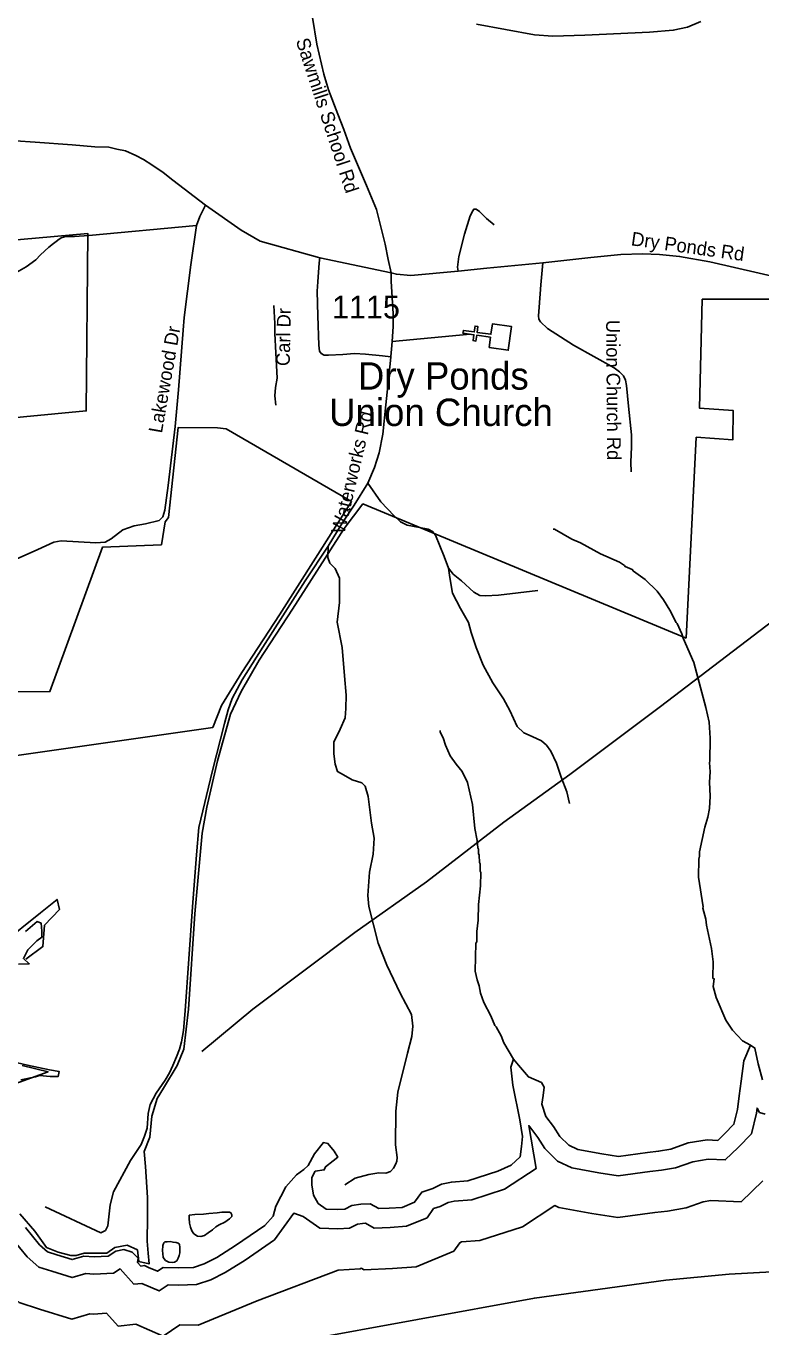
# Model space of a CAD drawing. Extents: x 1159738 to 1321356, y 736314 to 882035.
# Drawn here: x 1262980 to 1267008, y 749048 to 756175 of the extents above; entities that cross this region are included whole.
import ezdxf

# ---------------------------------------------------------------- set-up
doc = ezdxf.new("R2010")
doc.units = 0
for name, color, linetype in [('Exist Boundary Political City Limit New', 7, 'Continuous'), ('Exist Boundary Political CountyLine', 7, 'Continuous'), ('Exist Cultural Church CELL', 7, 'Continuous'), ('Exist Cultural Church Label', 7, 'Continuous'), ('Exist Hydrographic Buffer Line', 7, 'Continuous'), ('Exist Hydrographic Lake Shore', 7, 'Continuous'), ('Exist Hydrographic Misc Water Feature', 7, 'Continuous'), ('Exist Road Non-System Type 51', 7, 'Continuous'), ('Exist Road Non-System Type 51 Label', 7, 'Continuous'), ('Exist Road Secondary Type 51 Attributed', 7, 'Continuous'), ('Exist Road Secondary Type 51 Label', 7, 'Continuous'), ('Exist Road Secondary Type 51 Number Label', 7, 'Continuous'), ('Exist Utilities Electrical Transmission Line', 7, 'Continuous'), ('Map Preparation Boundary City Limit Buffer Line', 7, 'Continuous')]:
    doc.layers.add(name, color=color, linetype=linetype)

msp = doc.modelspace()

# ---------------------------------------------------------------- linework, layer by layer
at = {"layer": 'Exist Boundary Political City Limit New'}
for points in [[(1262145.2, 753954.7), (1263309.9, 754066.5), (1263318.5, 755038.6), (1262292, 754947.9)], [(1267932.2, 754678), (1266685.8, 754678), (1266670.3, 754081.6), (1266855.1, 754068.7), (1266854.7, 753908.1), (1266653.1, 753922.4), (1266597.3, 752821.4)], [(1262276.5, 752084.9), (1264003.4, 752333), (1264050.7, 752453.4), (1264162.4, 752634.1), (1264368.7, 752950.2), (1264764.1, 753569.5), (1264076.7, 753968.4), (1264030, 753973.5), (1263813.2, 753974.9), (1263761.6, 753482.5), (1263742.3, 753458.8), (1263721.9, 753333), (1263399.5, 753320.1), (1263111.5, 752528.7), (1262428.2, 752524.4)], [(1266597.3, 752821.4), (1264826.5, 753556.9), (1264723.3, 753421.4), (1264440.2, 752980.1), (1264257.5, 752700.6), (1264158.6, 752528.5), (1264100.6, 752406), (1264029.9, 752149.2), (1263971.9, 751895.4), (1263946.1, 751753.5), (1263905.3, 751311.5), (1263870.9, 750788.9), (1263845.1, 750569.6), (1263809, 750481), (1263733.8, 750356.3), (1263699.4, 750300.4), (1263669.3, 750203.6), (1263658.6, 750087.5), (1263628.5, 750010.1), (1263635, 749927.1), (1263645.7, 749757.2), (1263645.7, 749647.5), (1263643.6, 749518.5), (1263650, 749451.8), (1263654.3, 749393.8), (1263598.5, 749406.7), (1263590.9, 749470.1), (1263535.1, 749495.9), (1263466.3, 749483), (1263423.3, 749452.9), (1263376, 749452.9), (1263298.7, 749452.9), (1263255.7, 749440), (1263225.6, 749440), (1263156.8, 749457.2), (1263092.4, 749483), (1263027.9, 749573.3), (1262946.2, 749667.9)], [(1262978.5, 751063.6), (1263073, 751132.4), (1263081.6, 751248.6), (1263163.3, 751334.6), (1263150.4, 751390.5), (1263060.1, 751317.4), (1262845.2, 751145.3)], [(1262899, 750373.3), (1263101, 750446.4), (1262959.1, 750480.8)]]:
    msp.add_lwpolyline(points, dxfattribs=at)
at = {"layer": 'Exist Boundary Political CountyLine'}
msp.add_lwpolyline([(1275487.7, 746396.7), (1275208.4, 749051.3), (1275206, 749131.4), (1275197.6, 749211.6), (1275176.8, 749268.1), (1275147.5, 749306.7), (1275000.3, 749445.7), (1274913.6, 749513.5), (1274703.9, 749631.8), (1274606.5, 749663.7), (1274512.7, 749675.6), (1273414.6, 749697.7), (1266834.1, 749337.5), (1266487.3, 749304.4), (1265766.9, 749206.8), (1263842.9, 748855.2), (1262274.7, 748482.5)], dxfattribs=at)
at = {"layer": 'Exist Cultural Church CELL'}
msp.add_lwpolyline([(1265517.8, 754413.8), (1265525.7, 754470.2), (1265450.3, 754480.9), (1265445.8, 754449.3), (1265430, 754451.5), (1265434.5, 754483.2), (1265375, 754491.7), (1265377.2, 754507.6), (1265436.8, 754499.1), (1265441.3, 754530.7), (1265457.1, 754528.5), (1265452.6, 754496.8), (1265528, 754486), (1265536.2, 754543.1), (1265641.6, 754528), (1265623.1, 754398.7)], close=True, dxfattribs=at)
at = {"layer": 'Exist Hydrographic Buffer Line'}
for points in [[(1267031.8, 750213.2), (1267000.6, 750223.6), (1266986.7, 750246.9), (1266983.2, 750220.2), (1266955.4, 750105.5), (1266882.5, 750031.4), (1266812.3, 749963.4), (1266718.8, 749967.2), (1266635.3, 749953.7), (1266540.3, 749920.6), (1266462.6, 749906.6), (1266399, 749899.2), (1266226.3, 749875.9), (1266119, 749892.7), (1265971, 749919.3), (1265893.6, 749956.9), (1265823.2, 750025.2), (1265784.6, 750086.7), (1265735.1, 750151.7), (1265775.5, 749915.6), (1265603.4, 749802.8), (1265422.6, 749744.8), (1265326.8, 749737.3), (1265293.1, 749729.9), (1265250.4, 749708.1), (1265214.2, 749696.8), (1265178, 749646.4), (1265065.5, 749599.6), (1264975.6, 749593.6), (1264887.9, 749589.9), (1264841.4, 749616), (1264825.2, 749615.2), (1264797.3, 749611.2), (1264753.9, 749590.1), (1264688.6, 749586.2), (1264589.8, 749589.9), (1264499.8, 749652.9), (1264448.5, 749672.5), (1264342, 749525.3)], [(1263923.6, 749057.9), (1263823.9, 749059.8), (1263732.1, 748998.2), (1263582.1, 749063.7), (1263485.7, 749052), (1263421.7, 749122.9), (1263350.4, 749118.4), (1263330, 749120.2), (1263231.1, 749090.7), (1263055, 749145.9), (1262942, 749182.5), (1262828.9, 749280), (1262733.9, 749397), (1262697.7, 749441.7), (1262618.3, 749509.7), (1262443.9, 749710.6), (1262387.6, 749882.1)], [(1267018.5, 749848.9), (1266900, 749733.9), (1266732.4, 749740.7), (1266690.8, 749734), (1266597.8, 749701.6), (1266495.7, 749683.3), (1266427.2, 749675.3), (1266223.8, 749647.8), (1266081.5, 749670.1), (1265900.5, 749702.7), (1265878.6, 749713.3), (1265701.5, 749597.3), (1265466.6, 749521.9), (1265366.7, 749514), (1265357.4, 749509.3), (1265324, 749462.6), (1265117.7, 749376.9), (1264987.9, 749368.2), (1264833.3, 749361.7), (1264817.9, 749370.3), (1264812.2, 749367.5), (1264691.2, 749360.2), (1264247.8, 749191.3), (1263923.6, 749057.9)], [(1264342, 749525.3), (1264180.6, 749414.5), (1264072.5, 749347.1), (1263993.4, 749306), (1263914.1, 749280.3), (1263815.5, 749277.5), (1263759.7, 749279.1), (1263709.8, 749245.6), (1263614.8, 749287), (1263571.7, 749281.8), (1263495.8, 749366.1), (1263459.9, 749343.6), (1263352.7, 749336.8), (1263307.2, 749340.7), (1263232.7, 749318.5), (1263121.1, 749353.5), (1263050.9, 749376.2), (1262985.8, 749432.3), (1262903.1, 749534.2)]]:
    msp.add_lwpolyline(points, dxfattribs=at)
at = {"layer": 'Exist Hydrographic Lake Shore'}
for points in [[(1262939.9, 751035.4), (1262997.6, 751037.8), (1262965.7, 751066.4), (1262990.3, 751114), (1263039.4, 751164.1), (1263066.4, 751183.1), (1263066.4, 751216.5), (1263063.9, 751259.4), (1263041.8, 751268.9), (1262978, 751214.1)], [(1267017, 750401.6), (1266992.5, 750489.8), (1266975.3, 750575.6), (1266950.7, 750592.3), (1266913.9, 750506.5), (1266899.1, 750394.5), (1266889.3, 750313.5), (1266879.5, 750239.6), (1266859.8, 750158.6), (1266808.3, 750106.2), (1266771.4, 750070.5), (1266712.5, 750072.9), (1266609.3, 750056.2), (1266513.5, 750022.8), (1266447.2, 750010.9), (1266385.8, 750003.8), (1266227.4, 749982.3), (1266136.5, 749996.6), (1266003.9, 750020.4), (1265954.8, 750044.3), (1265905.7, 750091.9), (1265871.3, 750146.7), (1265829.5, 750201.5), (1265807.4, 750268.2), (1265814.8, 750315.9), (1265819.7, 750361.1), (1265805, 750387.4), (1265733.7, 750418.3), (1265679.7, 750482.7), (1265651.4, 750516), (1265636.7, 750470.7), (1265649, 750373.1), (1265685.8, 750182.5), (1265700.6, 750091.9), (1265695.7, 750037.1), (1265688.3, 749979.9), (1265639.2, 749934.7), (1265565.5, 749901.3), (1265402.1, 749848.9), (1265311.3, 749841.7), (1265257.2, 749829.8), (1265210.6, 749806), (1265149.2, 749786.9), (1265109.9, 749732.1), (1265041.1, 749703.5), (1264969.9, 749698.8), (1264913.4, 749696.4), (1264866.7, 749722.6), (1264815.1, 749720.2), (1264766, 749713.1), (1264726.7, 749694), (1264687.4, 749691.6), (1264624.8, 749694), (1264580.6, 749725), (1264556, 749770.3), (1264546.2, 749827.4), (1264546.2, 749867.9), (1264565.8, 749901.3), (1264615, 749908.5), (1264621.6, 749926.3), (1264663.6, 749959), (1264688.7, 749977.5), (1264669, 750010.9), (1264634.6, 750053.8), (1264610.1, 750058.6), (1264560.9, 749996.6), (1264526.5, 749932.3), (1264502, 749910.8), (1264462.7, 749882.2), (1264403.7, 749815.5), (1264349.7, 749710.7), (1264335, 749655.9), (1264288.3, 749603.5)], [(1262951, 750401.6), (1263032, 750418.3), (1263054.1, 750425.5), (1263113.1, 750420.7), (1263157.3, 750420.7), (1263162.2, 750446.9), (1263108.1, 750456.4), (1262989, 750482.7), (1262871.1, 750508.9)], [(1264288.3, 749603.5), (1264128.7, 749493.9), (1264025.5, 749429.5), (1263956.7, 749393.8), (1263897.8, 749374.7), (1263815.5, 749372.4), (1263732, 749374.7), (1263700.1, 749353.3), (1263650.9, 749374.7), (1263628.8, 749384.3), (1263609.2, 749381.9), (1263592, 749401), (1263594.5, 749424.8), (1263562.5, 749458.1), (1263515.9, 749472.4), (1263471.6, 749462.9), (1263429.9, 749436.7), (1263353.8, 749431.9), (1263297.3, 749436.7), (1263233.4, 749417.6), (1263149.9, 749443.8), (1263098.3, 749460.5), (1263054.1, 749498.6), (1262976.7, 749593.9)]]:
    msp.add_lwpolyline(points, dxfattribs=at)
at = {"layer": 'Exist Hydrographic Misc Water Feature'}
for points in [[(1266950.7, 750592.3), (1266907.3, 750616.2), (1266852.9, 750673.8), (1266816.4, 750728.8), (1266761.8, 750852.3), (1266746.7, 750913.5), (1266752.4, 750954.7), (1266746.7, 750956.8), (1266744.8, 750960.8), (1266745.2, 751048.8), (1266737.2, 751121), (1266708.8, 751249.8), (1266705.8, 751281.9), (1266690.2, 751342.1), (1266691.6, 751350.3), (1266665, 751511.8), (1266666.8, 751610.9), (1266671.3, 751626.8), (1266671.9, 751650.8), (1266699.7, 751785.9), (1266717.2, 751841.4), (1266726.6, 751889.1), (1266728.9, 751956.5), (1266726.6, 752033.1), (1266729.6, 752089.5), (1266725.5, 752141.1), (1266727.7, 752147), (1266729.2, 752272.9), (1266723.7, 752361.1), (1266705.9, 752441.6), (1266640.7, 752687.4), (1266582.4, 752821), (1266575, 752845.2), (1266548.6, 752902), (1266542.7, 752908.1), (1266508.6, 752975.1), (1266474.3, 753032.1), (1266439, 753078.6), (1266373.3, 753143), (1266309.3, 753187.8), (1266302.7, 753197), (1266263.3, 753214.1), (1266259.4, 753220.2), (1266231.9, 753237), (1266129.2, 753283.9), (1266018.7, 753343.1), (1265971.4, 753364.4), (1265876.8, 753419.1), (1265868.8, 753419.4)], [(1265651.4, 750516), (1265598.7, 750603.8), (1265583.7, 750642.2), (1265556.3, 750691.7), (1265549.3, 750699.2), (1265527.7, 750751.8), (1265488.8, 750824.9), (1265470.2, 750877.4), (1265463.3, 750917.5), (1265452.3, 750949.9), (1265441.6, 750998.2), (1265445.8, 751150), (1265450, 751157.9), (1265451.6, 751213.8), (1265459, 751276.8), (1265459.7, 751361.6), (1265470.5, 751465.2), (1265472.5, 751537.2), (1265468.8, 751545.3), (1265469.8, 751585.2), (1265466.1, 751593.3), (1265463.1, 751633.4), (1265459.5, 751641.5), (1265460.1, 751665.5), (1265456.3, 751673.6), (1265453.4, 751713.7), (1265439.2, 751778), (1265426.8, 751910.4), (1265400.2, 752031.1), (1265369.8, 752092), (1265336.9, 752130.9), (1265304.2, 752177.8), (1265279.8, 752234.5), (1265266.9, 752274.9), (1265249.8, 752307.4), (1265250.1, 752315.3)], [(1263874.9, 749661.2), (1263905.4, 749663.7), (1263952.9, 749666.7), (1263982, 749668.9), (1264027.9, 749673.3), (1264052.5, 749677), (1264073.1, 749677.7), (1264095.4, 749676.2), (1264103.1, 749672.7), (1264108.7, 749662.4), (1264107.9, 749653.3), (1264095.5, 749640.2), (1264069.5, 749623.2), (1264039.1, 749607.3), (1264021.4, 749597), (1264001.8, 749580.2), (1263979.4, 749564.1), (1263957.9, 749549.3), (1263937.8, 749543.6), (1263920.5, 749546.3), (1263899.2, 749559.3), (1263888.2, 749575.2), (1263882.1, 749594.3), (1263877.1, 749617.3), (1263873.5, 749643.6), (1263874.9, 749661.2)], [(1263727.9, 749464.5), (1263729.9, 749495), (1263735.1, 749508.4), (1263740.7, 749513.7), (1263753.3, 749515.3), (1263770, 749515.6), (1263786.1, 749512.6), (1263803.9, 749510.2), (1263814.3, 749506.7), (1263819.3, 749503.1), (1263821.8, 749497.4), (1263822.7, 749486.5), (1263823.3, 749467.8), (1263822.8, 749454.8), (1263820, 749440.3), (1263814.5, 749425.6), (1263806.5, 749410.2), (1263794.7, 749402.8), (1263780.4, 749402), (1263763.8, 749402.8), (1263745.1, 749412.3), (1263731.8, 749427.9), (1263729.7, 749450.9), (1263727.9, 749464.5)]]:
    msp.add_lwpolyline(points, dxfattribs=at)
at = {"layer": 'Exist Road Non-System Type 51'}
msp.add_line((1264986.4, 754447), (1265415.1, 754486.8), dxfattribs=at)
for points in [[(1266678, 756198.8), (1266605.7, 756167.9), (1266527.5, 756152), (1266397.5, 756140.5), (1266042, 756124.2), (1265867.6, 756119), (1265767.7, 756127.2), (1265449.9, 756185.5)], [(1263964.1, 755193.3), (1263932.4, 755130.9), (1263913.8, 755083)], [(1265347.8, 754831.8), (1265344.6, 754853.6), (1265352.9, 754912), (1265382.9, 755035.4), (1265414.6, 755135.5), (1265429.6, 755162.2), (1265434.6, 755172.2), (1265447.9, 755172.2), (1265464.6, 755158.8), (1265504.6, 755120.5), (1265546.3, 755085.4)], [(1262677, 753246.5), (1262825.9, 753235.1), (1262865.2, 753235.1), (1262909, 753247.1), (1263044.6, 753307.3), (1263132.7, 753347.8), (1263173.2, 753355.5), (1263362.4, 753343.4), (1263414.9, 753346.7), (1263446.6, 753366.4), (1263511.1, 753414.5), (1263572.3, 753436.4), (1263635.7, 753448.5), (1263710.6, 753467), (1263730.3, 753485.6), (1263741.3, 753522.8), (1263759.8, 753658.5), (1263797, 753980.5), (1263816.7, 754181.2), (1263840.8, 754508.4), (1263847.1, 754577.4), (1263883.2, 754867.4), (1263913.8, 755083)], [(1263155.3, 755002.7), (1263172.2, 755014), (1263190.3, 755019.6), (1263210.4, 755021.2), (1263246.4, 755022.5), (1263324.5, 755026.9), (1263913.8, 755083)], [(1262657.4, 754681.6), (1262788.2, 754752), (1262878.8, 754797.4), (1262980.8, 754856.4), (1263033.7, 754894.7), (1263060.3, 754922.2), (1263105.2, 754963.3), (1263131.6, 754982.8), (1263151.9, 755000.4), (1263155.3, 755002.7)], [(1264590.2, 754904.1), (1264586, 754878.2), (1264579.4, 754774), (1264575.2, 754722.3), (1264580.2, 754587.1), (1264585.2, 754425.8), (1264589.4, 754394.1), (1264598.5, 754380.8), (1264614.4, 754371.6), (1264637.7, 754371.6), (1264716.9, 754375.8), (1264781.1, 754380.8), (1264840.2, 754377.5), (1264933.6, 754367.5), (1264979.4, 754362.5)], [(1265812.1, 754878.4), (1265802.1, 754757.6), (1265793.3, 754634.4), (1265789.2, 754587.2), (1265790.6, 754569.5), (1265799.4, 754553.8), (1265838.2, 754517.1), (1265981, 754427.3), (1266203.7, 754302.4), (1266232.3, 754281.3), (1266255.4, 754258.8), (1266264.9, 754235.7), (1266271.6, 754206), (1266282.4, 754091.7), (1266298, 753934.9), (1266299.3, 753869.9), (1266294.6, 753784.9), (1266296.6, 753731.8)], [(1264982.1, 754823), (1264980.6, 754777.1), (1264992.6, 754599.1), (1264991.9, 754528.7), (1264986.4, 754447)], [(1264338.7, 754644.4), (1264343.6, 754545.9), (1264343.6, 754490.8), (1264350.2, 754384.1), (1264356.9, 754245.6), (1264346.9, 754193.9), (1264343.6, 754148.9), (1264348.6, 754098.8)], [(1264986.4, 754447), (1264978.4, 754343.2), (1264953, 754100.3), (1264935.7, 753938.4), (1264916.2, 753837), (1264889.2, 753755.6), (1264853.2, 753670.7)], [(1264853.2, 753670.7), (1264778.1, 753550.6), (1264712.1, 753450.7), (1264635.7, 753326.1), (1264510.3, 753135.3), (1264277.2, 752772.4), (1264165.5, 752593.6), (1264110.7, 752490.6), (1264088.2, 752429), (1264067.9, 752353.2), (1264001.9, 752096), (1263927.7, 751784.1), (1263914.9, 751634.1), (1263892.4, 751349), (1263851.9, 750779.1), (1263843.7, 750672.2), (1263832.5, 750609.9), (1263821.9, 750570.8), (1263804.7, 750528.8), (1263785.2, 750479.9), (1263766.4, 750440.9), (1263742.5, 750400), (1263693, 750328.6), (1263661.5, 750267.8), (1263649.5, 750218.2), (1263643.4, 750137), (1263630, 750093.4), (1263610.5, 750048.3), (1263553.5, 749959.6), (1263459.4, 749788.9), (1263440.8, 749716.5), (1263429.1, 749602.1), (1263415.1, 749576.4), (1263389.4, 749564.7), (1263086, 749707.2)], [(1264853.2, 753670.7), (1264924.3, 753568.7), (1264997.2, 753491.4), (1265032.5, 753458.2), (1265068.5, 753441.3), (1265137, 753427.3), (1265184.8, 753418.5), (1265208.3, 753406.7), (1265224.5, 753385.4), (1265271.3, 753268.7), (1265296.3, 753205.4), (1265321.3, 753171.5), (1265366.9, 753134.7), (1265435.2, 753073.9), (1265467.6, 753055.5), (1265498.5, 753052.6), (1265569.1, 753057.7), (1265785.4, 753082.8)], [(1264728.1, 749827.7), (1264784.5, 749864), (1264858.9, 749884.1), (1264913.3, 749892.2), (1264951.5, 749890.1), (1264977.7, 749900.2), (1264993.8, 749918.3), (1265007.8, 749942.5), (1265011.9, 749956.6), (1265013.9, 749976.7), (1265005.8, 750045.2), (1265007.8, 750230.5), (1265017.9, 750335.2), (1265070.2, 750548.6), (1265094.4, 750639.2), (1265100.4, 750695.6), (1265092.4, 750760.1), (1265030, 750876.9), (1264957.6, 751030.6), (1264909.3, 751151.4), (1264859, 751350.8), (1264852.9, 751411.2), (1264863, 751540.1), (1264883.1, 751638.7), (1264889.1, 751726.1), (1264873, 751808.7), (1264854.9, 751953.7), (1264838.8, 752010), (1264820.7, 752028.2), (1264768.4, 752046.3), (1264720.1, 752072.5), (1264687.9, 752090.6), (1264673.8, 752130.9), (1264667.7, 752187.2), (1264667.7, 752251.7), (1264702, 752322.2), (1264730.1, 752385.1), (1264732.1, 752435.5), (1264734.2, 752510), (1264726.1, 752614.7), (1264712, 752769.7), (1264685.9, 752908.7), (1264697.9, 753017.4), (1264697.9, 753150.3), (1264673.9, 753203.9), (1264645.7, 753232.1), (1264633.6, 753264.3), (1264635.7, 753326.1)], [(1265296.3, 753205.4), (1265302.8, 753153.2), (1265317.8, 753068.1), (1265361.1, 752984.7), (1265404.4, 752908), (1265419.4, 752852.9), (1265447.8, 752769.5), (1265486.1, 752672.8), (1265539.4, 752576), (1265597.8, 752489.3), (1265632.4, 752425.1), (1265672.5, 752336.7), (1265709.1, 752303.3), (1265754.1, 752283.3), (1265805.8, 752260), (1265832.5, 752234.9), (1265855.8, 752203.2), (1265887.5, 752136.5), (1265912.5, 752059.8), (1265944.1, 751980.2), (1265959.1, 751915.1)]]:
    msp.add_lwpolyline(points, dxfattribs=at)
at = {"layer": 'Exist Road Secondary Type 51 Attributed'}
for points in [[(1264551.1, 756220.9), (1264574.2, 756076.2), (1264612.3, 755910.5), (1264638.8, 755826), (1264688.6, 755691.9), (1264722.9, 755607.2), (1264758.9, 755506.4), (1264846.8, 755300.5), (1264900.2, 755169.4), (1264949.2, 754980.5), (1264965.7, 754895.6), (1264982.1, 754823)], [(1264982.1, 754823), (1264590.2, 754904.1), (1264263.6, 754995.8), (1264160.2, 755056.7), (1263964.1, 755193.3), (1263784.8, 755329.8), (1263731.8, 755371.9), (1263669.7, 755415), (1263623.5, 755443.7), (1263581.3, 755465.9), (1263525.5, 755491.4), (1263477.7, 755500.3), (1263434.7, 755510.5), (1263358.2, 755513.7), (1263233.9, 755524.9), (1263030, 755539.2), (1262813.3, 755553.6)], [(1267132.5, 754790.2), (1266728.7, 754882.8), (1266561.9, 754913.1), (1266452.8, 754923.8), (1266359.3, 754926.7), (1266239.7, 754923.9), (1266075, 754907.3), (1265812.1, 754878.4), (1265505.3, 754848.3), (1265347.8, 754831.8), (1265089.8, 754808.1), (1265010.6, 754814.7), (1264982.1, 754823)]]:
    msp.add_lwpolyline(points, dxfattribs=at)
at = {"layer": 'Exist Utilities Electrical Transmission Line'}
msp.add_lwpolyline([(1263942.9, 750557.2), (1264223, 750789.3), (1264781.4, 751208.3), (1265174.8, 751487.3), (1265598.9, 751814.4), (1265960.9, 752073.8), (1266457.7, 752447.6), (1267072.6, 752916.4), (1267512.8, 752912.9), (1267999.4, 752924.9), (1268679.4, 752930.4), (1269442.3, 752935.8), (1269930.3, 752946.8), (1270629.5, 752928.6), (1271134.5, 752936.8), (1271434.7, 752941.7), (1271633.3, 752937.8), (1271709.9, 752939.2)], dxfattribs=at)
at = {"layer": 'Map Preparation Boundary City Limit Buffer Line'}
for points in [[(1262145.2, 753954.7), (1263309.9, 754066.5), (1263318.5, 755038.6), (1262292, 754947.9)], [(1267932.2, 754678), (1266685.8, 754678), (1266670.3, 754081.6), (1266855.1, 754068.7), (1266854.7, 753908.1), (1266653.1, 753922.4), (1266597.3, 752821.4)], [(1262276.5, 752084.9), (1264003.4, 752333), (1264050.7, 752453.4), (1264162.4, 752634.1), (1264368.7, 752950.2), (1264764.1, 753569.5), (1264076.7, 753968.4), (1264030, 753973.5), (1263813.2, 753974.9), (1263761.6, 753482.5), (1263742.3, 753458.8), (1263721.9, 753333), (1263399.5, 753320.1), (1263111.5, 752528.7), (1262428.2, 752524.4)], [(1266597.3, 752821.4), (1264826.5, 753556.9), (1264723.3, 753421.4), (1264440.2, 752980.1), (1264257.5, 752700.6), (1264158.6, 752528.5), (1264100.6, 752406), (1264029.9, 752149.2), (1263971.9, 751895.4), (1263946.1, 751753.5), (1263905.3, 751311.5), (1263870.9, 750788.9), (1263845.1, 750569.6), (1263809, 750481), (1263733.8, 750356.3), (1263699.4, 750300.4), (1263669.3, 750203.6), (1263658.6, 750087.5), (1263628.5, 750010.1), (1263635, 749927.1), (1263645.7, 749757.2), (1263645.7, 749647.5), (1263643.6, 749518.5), (1263650, 749451.8), (1263654.3, 749393.8), (1263598.5, 749406.7), (1263590.9, 749470.1), (1263535.1, 749495.9), (1263466.3, 749483), (1263423.3, 749452.9), (1263376, 749452.9), (1263298.7, 749452.9), (1263255.7, 749440), (1263225.6, 749440), (1263156.8, 749457.2), (1263092.4, 749483), (1263027.9, 749573.3), (1262946.2, 749667.9)], [(1262978.5, 751063.6), (1263073, 751132.4), (1263081.6, 751248.6), (1263163.3, 751334.6), (1263150.4, 751390.5), (1263060.1, 751317.4), (1262845.2, 751145.3)], [(1262899, 750373.3), (1263101, 750446.4), (1262959.1, 750480.8)]]:
    msp.add_lwpolyline(points, dxfattribs=at)

# ---------------------------------------------------------------- texts
at = {"layer": 'Exist Cultural Church Label'}
for s, p in [('Dry Ponds ', (1264798.8, 754183.1)), ('Union Church', (1264641.2, 753983.9))]:
    msp.add_text(s, height=150, dxfattribs=at).set_placement(p)
at = {"layer": 'Exist Road Non-System Type 51 Label'}
for s, rotation, p in [('Carl Dr', 88.86642, (1264425.3, 754311.5)), ('Lakewood Dr', 80.0501, (1263724.8, 753941.3)), ('Union Church Rd', 270.44363, (1266159.2, 754565.2)), ('Waterworks Rd', 76.66003, (1264724, 753387.7))]:
    msp.add_text(s, height=75, rotation=rotation, dxfattribs=at).set_placement(p)
at = {"layer": 'Exist Road Secondary Type 51 Label'}
for s, rotation, p in [('Sawmills School Rd', 288.16423, (1264457.8, 756095.1)), ('Dry Ponds Rd', 352.01213, (1266293, 754973.9))]:
    msp.add_text(s, height=75, rotation=rotation, dxfattribs=at).set_placement(p)
at = {"layer": 'Exist Road Secondary Type 51 Number Label'}
msp.add_text('1115', height=125, dxfattribs=at).set_placement((1264657.4, 754573.2))

doc.saveas('drawing.dxf')
